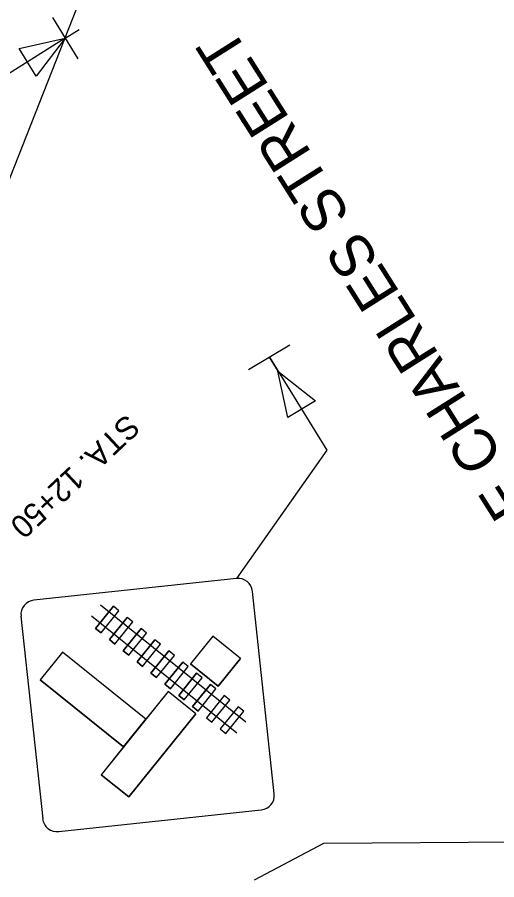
# Model space of a CAD drawing. Extents: x 1487362 to 2061618, y 497428 to 671257.
# Drawn here: x 1488565.8 to 1488633.1, y 499115 to 499236.2 of the extents above; entities that cross this region are included whole.
import ezdxf

# ---------------------------------------------------------------- set-up
doc = ezdxf.new("R2010")
doc.units = 0
for name, color, linetype in [('Exist Support 1', 7, 'Continuous'), ('Prop Horizontal Alignment Direction Label', 7, 'Continuous'), ('Prop Sign E Ped Crossing CELL', 7, 'Continuous'), ('Prop Support One', 7, 'Continuous'), ('Text', 7, 'Continuous')]:
    doc.layers.add(name, color=color, linetype=linetype)

msp = doc.modelspace()

# ---------------------------------------------------------------- linework, layer by layer
at = {"layer": 'Exist Support 1'}
for p, q in [((1488583.33, 499260.94), (1488557.34, 499194.94)), ((1488608.82, 499120.19), (1488730.91, 499121.07)), ((1488599.06, 499115.04), (1488608.82, 499120.19))]:
    msp.add_line(p, q, dxfattribs=at)
at = {"layer": 'Prop Sign E Ped Crossing CELL'}
for p, q in [((1488596.55, 499157.36), (1488568.1, 499154.31)), ((1488601.84, 499127.1), (1488598.8, 499155.55)), ((1488576.75, 499150.34), (1488579.26, 499153.46)), ((1488579.26, 499153.46), (1488576.75, 499150.34)), ((1488597.87, 499137.17), (1488577.47, 499153.62)), ((1488580.04, 499152.83), (1488579.26, 499153.46)), ((1488580.04, 499152.83), (1488579.26, 499153.46)), ((1488566.29, 499152.07), (1488569.34, 499123.61)), ((1488596.61, 499135.61), (1488576.21, 499152.06)), ((1488577.53, 499149.72), (1488580.04, 499152.83)), ((1488577.53, 499149.72), (1488580.04, 499152.83)), ((1488578.7, 499148.77), (1488581.21, 499151.89)), ((1488581.21, 499151.89), (1488578.7, 499148.77)), ((1488579.48, 499148.15), (1488581.99, 499151.26)), ((1488579.48, 499148.15), (1488581.99, 499151.26)), ((1488581.99, 499151.26), (1488581.21, 499151.89)), ((1488581.99, 499151.26), (1488581.21, 499151.89)), ((1488577.53, 499149.72), (1488576.75, 499150.34)), ((1488576.75, 499150.34), (1488577.53, 499149.72)), ((1488580.65, 499147.21), (1488583.16, 499150.32)), ((1488583.16, 499150.32), (1488580.65, 499147.21)), ((1488581.42, 499146.58), (1488583.93, 499149.69)), ((1488581.42, 499146.58), (1488583.93, 499149.69)), ((1488583.93, 499149.69), (1488583.16, 499150.32)), ((1488583.93, 499149.69), (1488583.16, 499150.32)), ((1488579.48, 499148.15), (1488578.7, 499148.77)), ((1488578.7, 499148.77), (1488579.48, 499148.15)), ((1488582.59, 499145.64), (1488585.1, 499148.75)), ((1488585.1, 499148.75), (1488582.59, 499145.64)), ((1488585.88, 499148.12), (1488585.1, 499148.75)), ((1488585.88, 499148.12), (1488585.1, 499148.75)), ((1488593.23, 499149.26), (1488590.09, 499145.37)), ((1488593.23, 499149.26), (1488590.09, 499145.37)), ((1488597.12, 499146.13), (1488593.23, 499149.26)), ((1488597.12, 499146.13), (1488593.23, 499149.26)), ((1488581.42, 499146.58), (1488580.65, 499147.21)), ((1488580.65, 499147.21), (1488581.42, 499146.58)), ((1488583.37, 499145.01), (1488585.88, 499148.12)), ((1488583.37, 499145.01), (1488585.88, 499148.12)), ((1488584.54, 499144.07), (1488587.05, 499147.18)), ((1488587.05, 499147.18), (1488584.54, 499144.07)), ((1488587.83, 499146.55), (1488587.05, 499147.18)), ((1488587.83, 499146.55), (1488587.05, 499147.18)), ((1488572.13, 499147), (1488568.99, 499143.11)), ((1488572.13, 499147), (1488568.99, 499143.11)), ((1488583.81, 499137.59), (1488572.13, 499147)), ((1488583.81, 499137.59), (1488572.13, 499147)), ((1488585.32, 499143.44), (1488587.83, 499146.55)), ((1488585.32, 499143.44), (1488587.83, 499146.55)), ((1488597.12, 499146.13), (1488593.98, 499142.23)), ((1488593.98, 499142.23), (1488597.12, 499146.13)), ((1488583.37, 499145.01), (1488582.59, 499145.64)), ((1488582.59, 499145.64), (1488583.37, 499145.01)), ((1488586.48, 499142.5), (1488588.99, 499145.61)), ((1488588.99, 499145.61), (1488586.48, 499142.5)), ((1488587.26, 499141.87), (1488589.77, 499144.98)), ((1488587.26, 499141.87), (1488589.77, 499144.98)), ((1488589.77, 499144.98), (1488588.99, 499145.61)), ((1488589.77, 499144.98), (1488588.99, 499145.61)), ((1488593.98, 499142.23), (1488590.09, 499145.37)), ((1488590.09, 499145.37), (1488593.98, 499142.23)), ((1488585.32, 499143.44), (1488584.54, 499144.07)), ((1488584.54, 499144.07), (1488585.32, 499143.44)), ((1488588.43, 499140.93), (1488590.94, 499144.04)), ((1488590.94, 499144.04), (1488588.43, 499140.93)), ((1488591.72, 499143.41), (1488590.94, 499144.04)), ((1488591.72, 499143.41), (1488590.94, 499144.04)), ((1488580.67, 499133.7), (1488568.99, 499143.11)), ((1488568.99, 499143.11), (1488580.67, 499133.7)), ((1488587.26, 499141.87), (1488586.48, 499142.5)), ((1488586.48, 499142.5), (1488587.26, 499141.87)), ((1488589.21, 499140.3), (1488591.72, 499143.41)), ((1488589.21, 499140.3), (1488591.72, 499143.41)), ((1488589.21, 499140.3), (1488591.72, 499143.41)), ((1488590.38, 499139.36), (1488592.89, 499142.47)), ((1488592.89, 499142.47), (1488590.38, 499139.36)), ((1488593.66, 499141.84), (1488592.89, 499142.47)), ((1488593.66, 499141.84), (1488592.89, 499142.47)), ((1488586.95, 499141.48), (1488577.53, 499129.8)), ((1488590.84, 499138.34), (1488586.95, 499141.48)), ((1488590.84, 499138.34), (1488586.95, 499141.48)), ((1488591.15, 499138.73), (1488593.66, 499141.84)), ((1488591.15, 499138.73), (1488593.66, 499141.84)), ((1488589.21, 499140.3), (1488588.43, 499140.93)), ((1488588.43, 499140.93), (1488589.21, 499140.3)), ((1488594.83, 499140.9), (1488592.32, 499137.79)), ((1488593.1, 499137.16), (1488595.61, 499140.27)), ((1488595.61, 499140.27), (1488594.83, 499140.9)), ((1488591.15, 499138.73), (1488590.38, 499139.36)), ((1488590.38, 499139.36), (1488591.15, 499138.73)), ((1488596.78, 499139.33), (1488594.27, 499136.22)), ((1488595.05, 499135.59), (1488597.56, 499138.71)), ((1488597.56, 499138.71), (1488596.78, 499139.33)), ((1488580.67, 499133.7), (1488583.81, 499137.59)), ((1488590.84, 499138.34), (1488581.42, 499126.67)), ((1488581.42, 499126.67), (1488590.84, 499138.34)), ((1488592.32, 499137.79), (1488593.1, 499137.16)), ((1488594.27, 499136.22), (1488595.05, 499135.59)), ((1488581.42, 499126.67), (1488577.53, 499129.8)), ((1488577.53, 499129.8), (1488581.42, 499126.67)), ((1488571.58, 499121.8), (1488600.03, 499124.85))]:
    msp.add_line(p, q, dxfattribs=at)
msp.add_lwpolyline([(1488586.95, 499141.48), (1488583.81, 499137.59), (1488580.67, 499133.7), (1488577.53, 499129.8)], dxfattribs=at)
for centre, start, end in [((1488596.77, 499155.33), 6.1127, 96.1127), ((1488568.32, 499152.28), 96.1127, 186.1127), ((1488599.82, 499126.88), 276.1127, 6.1127), ((1488571.36, 499123.83), 186.1127, 276.1127)]:
    msp.add_arc(centre, 2.04, start, end, dxfattribs=at)
at = {"layer": 'Prop Support One'}
for p, q in [((1488574.31, 499230.34), (1488570.74, 499236.13)), ((1488572.51, 499233.26), (1488574.48, 499234.47)), ((1488572.51, 499233.26), (1488541.45, 499213.67)), ((1488566.02, 499231.8), (1488572.51, 499233.26)), ((1488572.51, 499233.26), (1488568.42, 499227.91)), ((1488568.42, 499227.91), (1488566.02, 499231.8)), ((1488598.21, 499186.69), (1488604.05, 499190.17)), ((1488601.15, 499188.44), (1488602.34, 499186.46)), ((1488601.18, 499188.46), (1488609.24, 499175.38)), ((1488603.73, 499179.96), (1488602.36, 499186.47)), ((1488602.36, 499186.47), (1488607.66, 499182.3)), ((1488607.66, 499182.3), (1488603.73, 499179.96))]:
    msp.add_line(p, q, dxfattribs=at)
msp.add_lwpolyline([(1488609.24, 499175.38), (1488596.55, 499157.36)], dxfattribs=at)

# ---------------------------------------------------------------- texts
at = {"layer": 'Prop Horizontal Alignment Direction Label'}
msp.add_text('-Y2- E CHARLES STREET', height=6, rotation=122.3106, dxfattribs=at).set_placement((1488647.47, 499153.35))
at = {"layer": 'Text'}
msp.add_text('STA. 12+50  -Y2-', height=3.2, rotation=223.0789, dxfattribs=at).set_placement((1488581.11, 499180.6))

doc.saveas('drawing.dxf')
